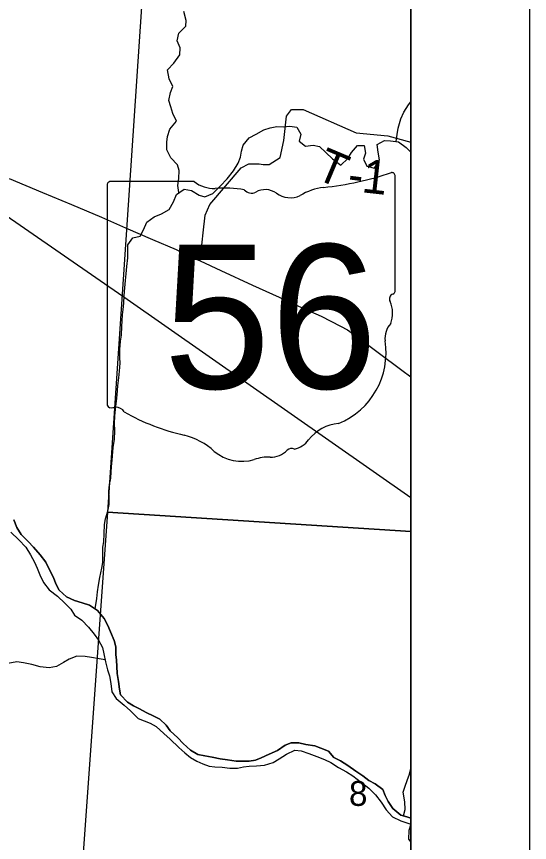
# Model space of a CAD drawing. Extents: x 0 to 42.5, y 0 to 22.
# Drawn here: x 8.567 to 9, y 14.792 to 15.489 of the extents above; entities that cross this region are included whole.
import ezdxf

# ---------------------------------------------------------------- set-up
doc = ezdxf.new("R2010")
doc.units = 0
for name, color, linetype in [('GM_X_Interchange_Ramps', 7, 'Continuous'), ('GM_X_Major_River', 7, 'Continuous'), ('GM_X_Minor_River', 7, 'Continuous'), ('GM_X_Rail_Line', 7, 'Continuous'), ('GM_X_Section_Text', 7, 'Continuous'), ('GM_X_State_Location', 7, 'Continuous'), ('GM_X_State_Route', 7, 'Continuous'), ('GM_X_State_Shield', 7, 'Continuous'), ('GM_X_Township_Road', 7, 'Continuous'), ('GM_X_Township_Road_Text', 7, 'Continuous'), ('GM_X_Unincorporated', 7, 'Continuous'), ('SH_Cut_Line', 7, 'Continuous'), ('SH_Data', 7, 'Continuous')]:
    doc.layers.add(name, color=color, linetype=linetype)

msp = doc.modelspace()

# ---------------------------------------------------------------- linework, layer by layer
at = {"layer": 'GM_X_Interchange_Ramps'}
msp.add_lwpolyline([(8.06989, 14.1), (8.9, 14.1), (8.9, 15.53758), (8.67633, 15.55354), (8.32394, 15.58239), (8.30432, 15.58399), (8.29687, 15.58461), (8.16884, 15.59509), (8.1568, 15.41315), (8.09551, 14.48695), (8.07289, 14.12804), (8.07009, 14.10263)], close=True, dxfattribs=at)
at = {"layer": 'GM_X_Major_River'}
for p, q in [((8.56762, 15.05781), (8.5652, 15.06427)), ((8.57136, 15.05191), (8.56762, 15.05781)), ((8.56267, 15.05386), (8.56925, 15.04737)), ((8.57719, 15.0458), (8.57136, 15.05191)), ((8.56925, 15.04737), (8.57526, 15.04107)), ((8.5817, 15.04103), (8.57719, 15.0458)), ((8.57526, 15.04107), (8.57919, 15.0346)), ((8.58733, 15.03474), (8.5817, 15.04103)), ((8.57919, 15.0346), (8.58255, 15.02851)), ((8.58255, 15.02851), (8.58479, 15.02356)), ((8.59202, 15.02845), (8.58733, 15.03474)), ((8.59463, 15.02312), (8.59202, 15.02845)), ((8.58479, 15.02356), (8.58702, 15.01767)), ((8.59818, 15.01608), (8.59463, 15.02312)), ((8.58702, 15.01767), (8.59019, 15.01139)), ((8.60078, 15.00962), (8.59818, 15.01608)), ((8.59019, 15.01139), (8.59488, 15.0051)), ((8.6034, 15.00486), (8.60078, 15.00962)), ((8.59488, 15.0051), (8.60185, 14.99975)), ((8.60942, 14.99913), (8.6034, 15.00486)), ((8.60185, 14.99975), (8.60805, 14.99383)), ((8.60805, 14.99383), (8.61313, 14.98887)), ((8.61621, 14.99624), (8.60942, 14.99913)), ((8.62283, 14.99411), (8.61621, 14.99624)), ((8.62906, 14.99218), (8.62283, 14.99411)), ((8.61313, 14.98887), (8.61632, 14.98392)), ((8.63566, 14.98777), (8.62906, 14.99218)), ((8.64129, 14.9811), (8.63566, 14.98777)), ((8.61632, 14.98392), (8.62253, 14.97951)), ((8.62253, 14.97951), (8.62798, 14.9736)), ((8.64447, 14.9752), (8.64129, 14.9811)), ((8.62798, 14.9736), (8.63286, 14.96788)), ((8.6467, 14.96969), (8.64447, 14.9752)), ((8.63286, 14.96788), (8.63661, 14.96273)), ((8.64986, 14.96246), (8.6467, 14.96969)), ((8.63661, 14.96273), (8.63979, 14.95665)), ((8.65115, 14.95695), (8.64986, 14.96246)), ((8.63979, 14.95665), (8.64107, 14.95114)), ((8.6511, 14.95069), (8.65115, 14.95695)), ((8.64107, 14.95114), (8.64254, 14.9443)), ((8.64254, 14.9443), (8.644, 14.93766)), ((8.65183, 14.94576), (8.6511, 14.95069)), ((8.65198, 14.94045), (8.65183, 14.94576)), ((8.644, 14.93766), (8.64586, 14.93271)), ((8.65212, 14.93457), (8.65198, 14.94045)), ((8.64586, 14.93271), (8.64695, 14.92607)), ((8.6534, 14.92792), (8.65212, 14.93457)), ((8.64695, 14.92607), (8.64766, 14.91924)), ((8.65411, 14.92147), (8.6534, 14.92792)), ((8.64766, 14.91924), (8.6514, 14.91352)), ((8.65521, 14.91653), (8.65411, 14.92147)), ((8.66085, 14.91043), (8.65521, 14.91653)), ((8.6514, 14.91352), (8.65818, 14.90779)), ((8.66594, 14.90736), (8.66085, 14.91043)), ((8.65818, 14.90779), (8.66345, 14.9032)), ((8.66345, 14.9032), (8.66984, 14.89672)), ((8.67122, 14.90467), (8.66594, 14.90736)), ((8.67669, 14.90179), (8.67122, 14.90467)), ((8.66984, 14.89672), (8.67494, 14.8946)), ((8.6833, 14.89871), (8.67669, 14.90179)), ((8.6882, 14.89603), (8.6833, 14.89871)), ((8.69346, 14.89087), (8.6882, 14.89603)), ((8.67494, 14.8946), (8.68003, 14.89267)), ((8.68003, 14.89267), (8.68513, 14.88998)), ((8.68513, 14.88998), (8.69171, 14.88406)), ((8.69703, 14.88611), (8.69346, 14.89087)), ((8.69171, 14.88406), (8.69698, 14.87928)), ((8.70342, 14.88019), (8.69703, 14.88611)), ((8.69698, 14.87928), (8.70431, 14.87222)), ((8.70793, 14.87542), (8.70342, 14.88019)), ((8.71414, 14.86988), (8.70793, 14.87542)), ((8.79901, 14.87597), (8.79389, 14.87411)), ((8.80545, 14.87612), (8.79901, 14.87597)), ((8.8115, 14.87475), (8.80545, 14.87612)), ((8.81888, 14.87357), (8.8115, 14.87475)), ((8.70431, 14.87222), (8.7092, 14.86764)), ((8.7092, 14.86764), (8.7141, 14.86362)), ((8.72018, 14.86624), (8.71414, 14.86988)), ((8.78761, 14.86959), (8.78058, 14.86661)), ((8.79389, 14.87411), (8.78761, 14.86959)), ((8.79516, 14.86651), (8.80219, 14.86988)), ((8.80219, 14.86988), (8.80749, 14.86947)), ((8.80749, 14.86947), (8.81391, 14.86715)), ((8.82398, 14.87164), (8.81888, 14.87357)), ((8.8304, 14.86894), (8.82398, 14.87164)), ((8.8349, 14.86379), (8.8304, 14.86894)), ((8.7141, 14.86362), (8.71957, 14.86055)), ((8.72623, 14.86525), (8.72018, 14.86624)), ((8.73247, 14.86388), (8.72623, 14.86525)), ((8.73908, 14.8627), (8.73247, 14.86388)), ((8.74533, 14.86171), (8.73908, 14.8627)), ((8.75251, 14.86072), (8.74533, 14.86171)), ((8.75762, 14.8605), (8.75251, 14.86072)), ((8.7635, 14.86065), (8.75762, 14.8605)), ((8.7688, 14.86156), (8.7635, 14.86065)), ((8.77374, 14.86343), (8.7688, 14.86156)), ((8.78058, 14.86661), (8.77374, 14.86343)), ((8.78394, 14.85938), (8.78888, 14.86257)), ((8.78888, 14.86257), (8.79516, 14.86651)), ((8.81391, 14.86715), (8.82071, 14.86464)), ((8.82071, 14.86464), (8.82713, 14.86213)), ((8.82713, 14.86213), (8.83241, 14.85944)), ((8.84056, 14.86091), (8.8349, 14.86379)), ((8.84678, 14.85708), (8.84056, 14.86091)), ((8.71957, 14.86055), (8.72447, 14.85825)), ((8.72447, 14.85825), (8.72976, 14.8565)), ((8.72976, 14.8565), (8.73468, 14.8559)), ((8.73468, 14.8559), (8.74093, 14.85567)), ((8.74093, 14.85567), (8.74736, 14.85487)), ((8.74736, 14.85487), (8.7538, 14.85483)), ((8.7538, 14.85483), (8.75892, 14.85575)), ((8.75892, 14.85575), (8.76365, 14.85629)), ((8.76365, 14.85629), (8.7699, 14.85662)), ((8.7699, 14.85662), (8.77653, 14.85715)), ((8.77653, 14.85715), (8.78394, 14.85938)), ((8.83241, 14.85944), (8.83882, 14.85542)), ((8.83882, 14.85542), (8.8458, 14.85177)), ((8.85356, 14.8521), (8.84678, 14.85708)), ((8.8458, 14.85177), (8.85089, 14.84833)), ((8.85089, 14.84833), (8.85823, 14.84259)), ((8.85941, 14.84827), (8.85356, 14.8521)), ((8.86449, 14.84426), (8.85941, 14.84827)), ((8.85823, 14.84259), (8.86463, 14.838)), ((8.86977, 14.84157), (8.86449, 14.84426)), ((8.87637, 14.83678), (8.86977, 14.84157)), ((8.86463, 14.838), (8.87008, 14.83227)), ((8.87822, 14.83165), (8.87637, 14.83678)), ((8.87008, 14.83227), (8.87496, 14.82598)), ((8.87496, 14.82598), (8.87908, 14.8197)), ((8.88084, 14.82651), (8.87822, 14.83165)), ((8.88477, 14.8208), (8.88084, 14.82651)), ((8.87908, 14.8197), (8.88453, 14.81359)), ((8.89155, 14.81507), (8.88477, 14.8208)), ((8.88453, 14.81359), (8.89151, 14.81033)), ((8.89646, 14.81371), (8.89155, 14.81507)), ((8.9, 14.81267), (8.89646, 14.81371)), ((8.89151, 14.81033), (8.89907, 14.80781)), ((8.89907, 14.80781), (8.9, 14.80761))]:
    msp.add_line(p, q, dxfattribs=at)
for points in [[(8.5652, 15.06427), (8.56762, 15.05781), (8.57136, 15.05191), (8.57719, 15.0458), (8.5817, 15.04103), (8.58733, 15.03474), (8.59202, 15.02845), (8.59463, 15.02312), (8.59818, 15.01608), (8.60078, 15.00962), (8.6034, 15.00486), (8.60942, 14.99913), (8.61621, 14.99624), (8.62283, 14.99411), (8.62906, 14.99218), (8.63566, 14.98777), (8.64129, 14.9811), (8.64447, 14.9752), (8.6467, 14.96969), (8.64986, 14.96246), (8.65115, 14.95695), (8.6511, 14.95069), (8.65183, 14.94576), (8.65198, 14.94045), (8.65212, 14.93457), (8.6534, 14.92792), (8.65411, 14.92147), (8.65521, 14.91653), (8.66085, 14.91043), (8.66594, 14.90736), (8.67122, 14.90467), (8.67669, 14.90179), (8.6833, 14.89871), (8.6882, 14.89603), (8.69346, 14.89087), (8.69703, 14.88611), (8.70342, 14.88019), (8.70793, 14.87542), (8.71414, 14.86988), (8.72018, 14.86624), (8.72623, 14.86525), (8.73247, 14.86388), (8.73908, 14.8627), (8.74533, 14.86171), (8.75251, 14.86072), (8.75762, 14.8605), (8.7635, 14.86065), (8.7688, 14.86156), (8.77374, 14.86343), (8.78058, 14.86661), (8.78761, 14.86959), (8.79389, 14.87411), (8.79901, 14.87597), (8.80545, 14.87612), (8.8115, 14.87475), (8.81888, 14.87357), (8.82398, 14.87164), (8.8304, 14.86894), (8.8349, 14.86379), (8.84056, 14.86091), (8.84678, 14.85708), (8.85356, 14.8521), (8.85941, 14.84827), (8.86449, 14.84426), (8.86977, 14.84157), (8.87637, 14.83678), (8.87822, 14.83165), (8.88084, 14.82651), (8.88477, 14.8208), (8.89155, 14.81507), (8.89646, 14.81371), (8.9, 14.81267)], [(8.56267, 15.05386), (8.56925, 15.04737), (8.57526, 15.04107), (8.57919, 15.0346), (8.58255, 15.02851), (8.58479, 15.02356), (8.58702, 15.01767), (8.59019, 15.01139), (8.59488, 15.0051), (8.60185, 14.99975), (8.60805, 14.99383), (8.61313, 14.98887), (8.61632, 14.98392), (8.62253, 14.97951), (8.62798, 14.9736), (8.63286, 14.96788), (8.63661, 14.96273), (8.63979, 14.95665), (8.64107, 14.95114), (8.64254, 14.9443), (8.644, 14.93766), (8.64586, 14.93271), (8.64695, 14.92607), (8.64766, 14.91924), (8.6514, 14.91352), (8.65818, 14.90779), (8.66345, 14.9032), (8.66984, 14.89672), (8.67494, 14.8946), (8.68003, 14.89267), (8.68513, 14.88998), (8.69171, 14.88406), (8.69698, 14.87928), (8.70431, 14.87222), (8.7092, 14.86764), (8.7141, 14.86362), (8.71957, 14.86055), (8.72447, 14.85825), (8.72976, 14.8565), (8.73468, 14.8559), (8.74093, 14.85567), (8.74736, 14.85487), (8.7538, 14.85483), (8.75892, 14.85575), (8.76365, 14.85629), (8.7699, 14.85662), (8.77653, 14.85715), (8.78394, 14.85938), (8.78888, 14.86257), (8.79516, 14.86651), (8.80219, 14.86988), (8.80749, 14.86947), (8.81391, 14.86715), (8.82071, 14.86464), (8.82713, 14.86213), (8.83241, 14.85944), (8.83882, 14.85542), (8.8458, 14.85177), (8.85089, 14.84833), (8.85823, 14.84259), (8.86463, 14.838), (8.87008, 14.83227), (8.87496, 14.82598), (8.87908, 14.8197), (8.88453, 14.81359), (8.89151, 14.81033), (8.89907, 14.80781), (8.9, 14.80761)]]:
    msp.add_lwpolyline(points, dxfattribs=at)
at = {"layer": 'GM_X_Minor_River'}
for p, q in [((8.71045, 15.48547), (8.70843, 15.49288)), ((8.70432, 15.4747), (8.71023, 15.48073)), ((8.71023, 15.48073), (8.71045, 15.48547)), ((8.70295, 15.46826), (8.70432, 15.4747)), ((8.70536, 15.46237), (8.70295, 15.46826)), ((8.70513, 15.45649), (8.70536, 15.46237)), ((8.70016, 15.44951), (8.70513, 15.45649)), ((8.69481, 15.44366), (8.70016, 15.44951)), ((8.69609, 15.43607), (8.69481, 15.44366)), ((8.69926, 15.42979), (8.69609, 15.43607)), ((8.69714, 15.42468), (8.69926, 15.42979)), ((8.69595, 15.41787), (8.69714, 15.42468)), ((8.69743, 15.41255), (8.69595, 15.41787)), ((8.69909, 15.40703), (8.69743, 15.41255)), ((8.89394, 15.40805), (8.89796, 15.41428)), ((8.89796, 15.41428), (8.9, 15.41673)), ((8.70226, 15.40038), (8.69909, 15.40703)), ((8.89144, 15.40238), (8.89394, 15.40805)), ((8.69673, 15.39378), (8.70226, 15.40038)), ((8.8893, 15.39462), (8.89144, 15.40238)), ((8.6946, 15.38753), (8.69673, 15.39378)), ((8.88831, 15.38931), (8.8893, 15.39462)), ((8.69418, 15.38279), (8.6946, 15.38753)), ((8.88753, 15.38327), (8.88831, 15.38931)), ((8.69414, 15.37635), (8.69418, 15.38279)), ((8.6975, 15.3695), (8.69414, 15.37635)), ((8.70314, 15.36377), (8.6975, 15.3695)), ((8.70443, 15.35883), (8.70314, 15.36377)), ((8.70419, 15.3522), (8.70443, 15.35883)), ((8.70339, 15.34632), (8.70419, 15.3522)), ((8.70436, 15.34021), (8.70339, 15.34632)), ((8.89996, 14.80762), (8.89827, 14.80213)), ((8.89827, 14.80213), (8.89784, 14.79492)), ((8.89784, 14.79492), (8.9, 14.79222))]:
    msp.add_line(p, q, dxfattribs=at)
for points in [[(8.6337, 14.98908), (8.63516, 14.99783), (8.63558, 15.00351), (8.63657, 15.0092), (8.63756, 15.01564), (8.63932, 15.0234), (8.64011, 15.02814), (8.64021, 15.04103), (8.641, 15.04577), (8.64143, 15.0524), (8.64167, 15.06037), (8.64246, 15.0651), (8.6444, 15.07154), (8.64539, 15.07722), (8.64543, 15.08196), (8.64528, 15.08841), (8.6457, 15.0941), (8.64688, 15.09921), (8.6471, 15.10433), (8.64752, 15.10907), (8.64793, 15.11456), (8.64877, 15.12518), (8.64996, 15.13219), (8.65039, 15.1392), (8.65005, 15.14565), (8.65028, 15.15153), (8.6509, 15.15759), (8.6517, 15.16441), (8.65231, 15.16972), (8.65293, 15.17711), (8.65355, 15.18393), (8.65416, 15.18962), (8.65478, 15.19644), (8.65443, 15.20119), (8.65448, 15.20801), (8.6551, 15.21483), (8.65589, 15.21995), (8.65613, 15.22716), (8.65655, 15.23208), (8.65677, 15.23701), (8.65719, 15.24175), (8.65798, 15.24687), (8.65822, 15.2535), (8.65864, 15.25976), (8.65926, 15.26601), (8.65987, 15.2717), (8.66048, 15.27795), (8.66129, 15.28515), (8.66113, 15.28989), (8.66118, 15.29615), (8.66539, 15.302), (8.67164, 15.30348), (8.67433, 15.30877), (8.67722, 15.3152), (8.6835, 15.31971), (8.68977, 15.32233), (8.69604, 15.32589), (8.69969, 15.33231), (8.7022, 15.33874), (8.70886, 15.34325), (8.71491, 15.34208), (8.72132, 15.33805), (8.72623, 15.33669), (8.73288, 15.33949), (8.73917, 15.34571), (8.74509, 15.35193), (8.75024, 15.35854), (8.75427, 15.36515), (8.7562, 15.37007), (8.75699, 15.37518), (8.75854, 15.3801), (8.76351, 15.38652), (8.7694, 15.38951), (8.77606, 15.39326), (8.78118, 15.39494), (8.78706, 15.39585), (8.79236, 15.39562), (8.79786, 15.39635), (8.80391, 15.39536), (8.80709, 15.38965), (8.80572, 15.38359), (8.81099, 15.37938), (8.81762, 15.38029), (8.82291, 15.37912), (8.82837, 15.37415), (8.83401, 15.36861), (8.84098, 15.36345), (8.8467, 15.36891), (8.84977, 15.37401), (8.85492, 15.37986), (8.8606, 15.38001), (8.86169, 15.37337), (8.85995, 15.36844), (8.86275, 15.36255), (8.86936, 15.3608), (8.87358, 15.36798), (8.8723, 15.37443), (8.87159, 15.3807), (8.87767, 15.38407), (8.88278, 15.38385), (8.88941, 15.38305)], [(8.88941, 15.38305), (8.896, 15.37826), (8.9, 15.37436)], [(8.64218, 14.94597), (8.63707, 14.94699), (8.63064, 14.94817), (8.62515, 14.94897), (8.61834, 14.9492), (8.61188, 14.94659), (8.60712, 14.94377), (8.60104, 14.9404), (8.59498, 14.9393), (8.58741, 14.9403), (8.58023, 14.94205), (8.57323, 14.94361), (8.56756, 14.94441), (8.56016, 14.94313)], [(8.89366, 14.81448), (8.89518, 14.81978), (8.89485, 14.82623), (8.89358, 14.83458), (8.89513, 14.83951), (8.89687, 14.84442), (8.8988, 14.84972), (8.9, 14.85452)]]:
    msp.add_lwpolyline(points, dxfattribs=at)
at = {"layer": 'GM_X_Rail_Line'}
msp.add_lwpolyline([(8.17938, 15.73019), (8.24138, 15.6602), (8.30262, 15.57959), (8.42318, 15.41403), (8.46804, 15.38328), (8.66065, 15.25025), (8.9, 15.08301)], dxfattribs=at)
at = {"layer": 'GM_X_State_Route'}
msp.add_lwpolyline([(8.5612, 15.3521), (8.58931, 15.34029), (8.61383, 15.33021), (8.63892, 15.31937), (8.65928, 15.31047), (8.68192, 15.30079), (8.70191, 15.29227), (8.71247, 15.28668), (8.72228, 15.2828), (8.73962, 15.27449), (8.7664, 15.26212), (8.78884, 15.25206), (8.80826, 15.24298), (8.82429, 15.23601), (8.84069, 15.22752), (8.84653, 15.22444), (8.85481, 15.21867), (8.87248, 15.20544), (8.89242, 15.19047), (8.9, 15.18493)], dxfattribs=at)
at = {"layer": 'GM_X_State_Shield'}
for p, q in [((8.71732, 15.3495), (8.64619, 15.3495)), ((8.88667, 15.25764), (8.88667, 15.35407)), ((8.6438, 15.34633), (8.6438, 15.162)), ((8.88664, 15.25767), (8.88667, 15.25764))]:
    msp.add_line(p, q, dxfattribs=at)
for centre, radius, start, end in [((8.80016, 15.60081), 0.25756, 275.84447, 288.90645), ((8.88397, 15.35447), 0.0027, 351.86209, 97.738), ((8.64659, 15.34672), 0.00281, 98.1301, 188.1301), ((8.73426, 15.3709), 0.02729, 231.61951, 271.11188), ((8.74331, 15.24602), 0.09797, 80.48669, 94.98827), ((8.76555, 15.34768), 0.00787, 219.79206, 297.10237), ((8.7771, 15.32637), 0.01637, 54.46668, 119.14113), ((8.83301, 15.2932), 0.05182, 97.34618, 120.76885), ((8.79823, 15.35559), 0.01969, 233.85621, 294.82819), ((8.88604, 15.25056), 0.00418, 107.94398, 210.33697), ((8.88378, 15.25727), 0.00289, 289.60381, 7.73413), ((8.85942, 15.23838), 0.02512, 340.03296, 23.64957), ((8.89636, 15.21729), 0.01827, 136.8065, 186.92959), ((8.81458, 15.20502), 0.06442, 292.30889, 8.98584), ((8.64661, 15.16159), 0.00284, 171.95839, 258.30661), ((8.64704, 15.18045), 0.02166, 267.33899, 280.60386), ((8.65147, 15.15136), 0.00781, 29.74838, 93.27175), ((8.75009, 15.31698), 0.18599, 240.41292, 257.1985), ((8.84175, 15.11025), 0.03528, 94.40312, 142.57675), ((8.69464, 15.07919), 0.05819, 47.18416, 75.83597), ((8.79705, 15.14413), 0.02081, 282.87319, 323.27711), ((8.75758, 15.15045), 0.03693, 230.70037, 286.29184), ((8.78161, 15.13664), 0.01967, 268.77702, 315.54927), ((8.79941, 15.11879), 0.00554, 65.75173, 132.64842), ((8.77891, 15.08672), 0.03034, 85.69512, 111.20995)]:
    msp.add_arc(centre, radius, start, end, dxfattribs=at)
at = {"layer": 'GM_X_Township_Road'}
msp.add_lwpolyline([(8.72228, 15.2828), (8.72491, 15.30642), (8.72647, 15.32122), (8.73048, 15.33032), (8.75677, 15.3612), (8.76323, 15.3646), (8.77196, 15.36439), (8.77538, 15.36381), (8.78051, 15.3638), (8.78963, 15.36985), (8.7929, 15.38427), (8.79505, 15.40476), (8.79943, 15.41044), (8.80911, 15.41042), (8.85386, 15.39058), (8.88062, 15.38824), (8.9, 15.38284)], dxfattribs=at)
at = {"layer": 'GM_X_Unincorporated'}
for points in [[(8.9, 15.05443), (8.9, 15.5396), (8.67682, 15.55582), (8.64401, 15.07062)], [(8.9, 14.54897), (8.9, 15.05443), (8.64401, 15.07062), (8.60812, 14.5665)]]:
    msp.add_lwpolyline(points, close=True, dxfattribs=at)
at = {"layer": 'SH_Cut_Line'}
msp.add_lwpolyline([(8.24781, 16.59008), (8.17933, 15.79111), (8.17776, 15.76158), (8.17561, 15.72139), (8.1727, 15.66691), (8.17075, 15.63044), (8.16995, 15.61544), (8.16884, 15.59509), (8.1568, 15.41315), (8.09551, 14.48695), (8.07289, 14.12804), (8.07009, 14.10263), (8.06989, 14.1), (8.9, 14.1), (8.9, 19.05381)], dxfattribs=at)
at = {"layer": 'SH_Data'}
for p, q in [((9, 21), (9, 14)), ((8.9, 20.9), (8.9, 14.1))]:
    msp.add_line(p, q, dxfattribs=at)

# ---------------------------------------------------------------- texts
at = {"layer": 'GM_X_Section_Text'}
msp.add_text('8', height=0.02093, rotation=0.00001, dxfattribs=at).set_placement((8.84778, 14.82292))
at = {"layer": 'GM_X_State_Location'}
for s in ['s', 'r']:
    msp.add_text(s, height=0.0000947, dxfattribs=at).set_placement((8.79975, 15.23617))
at = {"layer": 'GM_X_State_Shield'}
msp.add_text('56', height=0.121435, dxfattribs=at).set_placement((8.69126, 15.175))
at = {"layer": 'GM_X_Township_Road_Text'}
for s, rotation, p in [('T', 337.15367, (8.81804, 15.35257)), ('1', 353.66156, (8.85781, 15.34061)), ('-', 352.77407, (8.84575, 15.34213))]:
    msp.add_text(s, height=0.02841, rotation=rotation, dxfattribs=at).set_placement(p)

doc.saveas('drawing.dxf')
